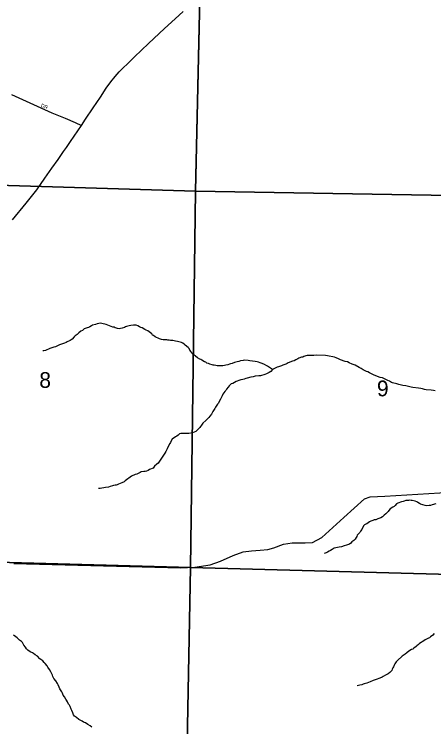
# Model space of a CAD drawing. Extents: x 0 to 34, y -2.3 to 22.
# Drawn here: x 3.889 to 5.006, y 17.952 to 19.85 of the extents above; entities that cross this region are included whole.
import ezdxf

# ---------------------------------------------------------------- set-up
doc = ezdxf.new("R2010")
doc.units = 0
for name, color, linetype in [('GM_X_Minor_River', 7, 'Continuous'), ('GM_X_Section', 7, 'Continuous'), ('GM_X_Section_Text', 7, 'Continuous'), ('GM_X_State_Route', 7, 'Continuous'), ('GM_X_Township_Road', 7, 'Continuous'), ('GM_X_Township_Subdivision', 7, 'Continuous'), ('GM_X_Township_Subdivision_Text', 7, 'Continuous')]:
    doc.layers.add(name, color=color, linetype=linetype)

msp = doc.modelspace()

# ---------------------------------------------------------------- linework, layer by layer
at = {"layer": 'GM_X_Minor_River'}
for p, q in [((4.0897, 19.0171), (4.0862, 19.0153)), ((4.0943, 19.02), (4.0897, 19.0171)), ((4.0974, 19.0214), (4.0943, 19.02)), ((4.1054, 19.0238), (4.0974, 19.0214)), ((4.1097, 19.0248), (4.1054, 19.0238)), ((4.1188, 19.0268), (4.1097, 19.0248)), ((4.126, 19.0255), (4.1188, 19.0268)), ((4.1298, 19.0246), (4.126, 19.0255)), ((4.1332, 19.0234), (4.1298, 19.0246)), ((4.1384, 19.0213), (4.1332, 19.0234)), ((4.1422, 19.0197), (4.1384, 19.0213)), ((4.1516, 19.0167), (4.1422, 19.0197)), ((4.155, 19.0159), (4.1516, 19.0167)), ((4.1576, 19.0147), (4.155, 19.0159)), ((4.182, 19.0158), (4.1762, 19.0137)), ((4.1847, 19.0169), (4.182, 19.0158)), ((4.1881, 19.0176), (4.1847, 19.0169)), ((4.1946, 19.0196), (4.1881, 19.0176)), ((4.1992, 19.021), (4.1946, 19.0196)), ((4.2061, 19.0216), (4.1992, 19.021)), ((4.2103, 19.0218), (4.2061, 19.0216)), ((4.2133, 19.0214), (4.2103, 19.0218)), ((4.2182, 19.0197), (4.2133, 19.0214)), ((4.2227, 19.0173), (4.2182, 19.0197)), ((4.2261, 19.0157), (4.2227, 19.0173)), ((4.2291, 19.0141), (4.2261, 19.0157)), ((4.0564, 18.9968), (4.0509, 18.9932)), ((4.0611, 19.0016), (4.0564, 18.9968)), ((4.0665, 19.0052), (4.0611, 19.0016)), ((4.0704, 19.0078), (4.0665, 19.0052)), ((4.0754, 19.0114), (4.0704, 19.0078)), ((4.0827, 19.0142), (4.0754, 19.0114)), ((4.0862, 19.0153), (4.0827, 19.0142)), ((4.1614, 19.0134), (4.1576, 19.0147)), ((4.164, 19.013), (4.1614, 19.0134)), ((4.1686, 19.0121), (4.164, 19.013)), ((4.172, 19.0127), (4.1686, 19.0121)), ((4.1762, 19.0137), (4.172, 19.0127)), ((4.2366, 19.0104), (4.2291, 19.0141)), ((4.2399, 19.0084), (4.2366, 19.0104)), ((4.2444, 19.0064), (4.2399, 19.0084)), ((4.2485, 19.0036), (4.2444, 19.0064)), ((4.2548, 18.9981), (4.2485, 19.0036)), ((4.2566, 18.995), (4.2548, 18.9981)), ((4.0373, 18.9807), (4.0299, 18.9771)), ((4.0427, 18.9839), (4.0373, 18.9807)), ((4.0486, 18.9906), (4.0427, 18.9839)), ((4.0509, 18.9932), (4.0486, 18.9906)), ((4.2593, 18.9942), (4.2566, 18.995)), ((4.2641, 18.9902), (4.2593, 18.9942)), ((4.2757, 18.9849), (4.2641, 18.9902)), ((4.281, 18.9833), (4.2757, 18.9849)), ((4.2852, 18.9827), (4.281, 18.9833)), ((4.289, 18.9823), (4.2852, 18.9827)), ((4.2947, 18.9821), (4.289, 18.9823)), ((4.2981, 18.9816), (4.2947, 18.9821)), ((4.3015, 18.9815), (4.2981, 18.9816)), ((4.3049, 18.981), (4.3015, 18.9815)), ((4.3075, 18.9806), (4.3049, 18.981)), ((4.311, 18.9805), (4.3075, 18.9806)), ((4.3147, 18.98), (4.311, 18.9805)), ((4.3178, 18.9791), (4.3147, 18.98)), ((4.3238, 18.9782), (4.3178, 18.9791)), ((4.331, 18.9761), (4.3238, 18.9782)), ((3.9838, 18.9598), (3.9803, 18.9577)), ((3.9938, 18.963), (3.9838, 18.9598)), ((3.9984, 18.964), (3.9938, 18.963)), ((4.0023, 18.9657), (3.9984, 18.964)), ((4.0096, 18.9693), (4.0023, 18.9657)), ((4.0176, 18.9717), (4.0096, 18.9693)), ((4.023, 18.9735), (4.0176, 18.9717)), ((4.0272, 18.9756), (4.023, 18.9735)), ((4.0299, 18.9771), (4.0272, 18.9756)), ((4.3344, 18.9752), (4.331, 18.9761)), ((4.3374, 18.974), (4.3344, 18.9752)), ((4.3411, 18.9712), (4.3374, 18.974)), ((4.3437, 18.9685), (4.3411, 18.9712)), ((4.3518, 18.9618), (4.3437, 18.9685)), ((4.3548, 18.959), (4.3518, 18.9618)), ((4.3566, 18.9552), (4.3548, 18.959)), ((3.9673, 18.9531), (3.9646, 18.9528)), ((3.9723, 18.9545), (3.9673, 18.9531)), ((3.9753, 18.9555), (3.9723, 18.9545)), ((3.9803, 18.9577), (3.9753, 18.9555)), ((4.3595, 18.9505), (4.3566, 18.9552)), ((4.3613, 18.9474), (4.3595, 18.9505)), ((4.3669, 18.9423), (4.3613, 18.9474)), ((4.3713, 18.9391), (4.3669, 18.9423)), ((4.669, 18.9405), (4.6656, 18.9395)), ((4.6804, 18.9409), (4.669, 18.9405)), ((4.6869, 18.9411), (4.6804, 18.9409)), ((4.693, 18.9413), (4.6869, 18.9411)), ((4.718, 18.9405), (4.693, 18.9413)), ((4.723, 18.9396), (4.718, 18.9405)), ((4.3765, 18.9348), (4.3713, 18.9391)), ((4.3833, 18.9312), (4.3765, 18.9348)), ((4.3859, 18.93), (4.3833, 18.9312)), ((4.3885, 18.9284), (4.3859, 18.93)), ((4.3956, 18.924), (4.3885, 18.9284)), ((4.3986, 18.9228), (4.3956, 18.924)), ((4.4019, 18.92), (4.3986, 18.9228)), ((4.4754, 18.922), (4.4692, 18.9195)), ((4.4826, 18.9237), (4.4754, 18.922)), ((4.4865, 18.9251), (4.4826, 18.9237)), ((4.4915, 18.9268), (4.4865, 18.9251)), ((4.498, 18.9278), (4.4915, 18.9268)), ((4.5014, 18.928), (4.498, 18.9278)), ((4.5113, 18.9277), (4.5014, 18.928)), ((4.5162, 18.9268), (4.5113, 18.9277)), ((4.5302, 18.9249), (4.5162, 18.9268)), ((4.5355, 18.924), (4.5302, 18.9249)), ((4.5393, 18.9231), (4.5355, 18.924)), ((4.5438, 18.9215), (4.5393, 18.9231)), ((4.5464, 18.9202), (4.5438, 18.9215)), ((4.6183, 18.9211), (4.6156, 18.9197)), ((4.6294, 18.9253), (4.6183, 18.9211)), ((4.6344, 18.9267), (4.6294, 18.9253)), ((4.6386, 18.9292), (4.6344, 18.9267)), ((4.6441, 18.9321), (4.6386, 18.9292)), ((4.6471, 18.9339), (4.6441, 18.9321)), ((4.6537, 18.936), (4.6471, 18.9339)), ((4.6571, 18.9363), (4.6537, 18.936)), ((4.6602, 18.9377), (4.6571, 18.9363)), ((4.6656, 18.9395), (4.6602, 18.9377)), ((4.7415, 18.9364), (4.723, 18.9396)), ((4.746, 18.9348), (4.7415, 18.9364)), ((4.7524, 18.9319), (4.746, 18.9348)), ((4.7572, 18.9291), (4.7524, 18.9319)), ((4.77, 18.9249), (4.7572, 18.9291)), ((4.7761, 18.9236), (4.77, 18.9249)), ((4.781, 18.9212), (4.7761, 18.9236)), ((4.7888, 18.9175), (4.781, 18.9212)), ((4.4061, 18.9191), (4.4019, 18.92)), ((4.4099, 18.9175), (4.4061, 18.9191)), ((4.4159, 18.9162), (4.4099, 18.9175)), ((4.4185, 18.9153), (4.4159, 18.9162)), ((4.4216, 18.9149), (4.4185, 18.9153)), ((4.4257, 18.914), (4.4216, 18.9149)), ((4.4291, 18.9135), (4.4257, 18.914)), ((4.4413, 18.9131), (4.4291, 18.9135)), ((4.4443, 18.9134), (4.4413, 18.9131)), ((4.4489, 18.9144), (4.4443, 18.9134)), ((4.4524, 18.9151), (4.4489, 18.9144)), ((4.4577, 18.9161), (4.4524, 18.9151)), ((4.4619, 18.9174), (4.4577, 18.9161)), ((4.465, 18.9189), (4.4619, 18.9174)), ((4.4692, 18.9195), (4.465, 18.9189)), ((4.5539, 18.9174), (4.5464, 18.9202)), ((4.5636, 18.9121), (4.5539, 18.9174)), ((4.5763, 18.9038), (4.5636, 18.9121)), ((4.5763, 18.9038), (4.572, 18.8986)), ((4.5887, 18.9095), (4.5763, 18.9038)), ((4.5921, 18.9105), (4.5887, 18.9095)), ((4.6005, 18.9129), (4.5921, 18.9105)), ((4.604, 18.9147), (4.6005, 18.9129)), ((4.6094, 18.9168), (4.604, 18.9147)), ((4.6121, 18.9179), (4.6094, 18.9168)), ((4.6156, 18.9197), (4.6121, 18.9179)), ((4.7971, 18.915), (4.7888, 18.9175)), ((4.8076, 18.9086), (4.7971, 18.915)), ((4.8124, 18.9058), (4.8076, 18.9086)), ((4.818, 18.9022), (4.8124, 18.9058)), ((4.8267, 18.8982), (4.818, 18.9022)), ((4.5191, 18.8831), (4.5091, 18.8807)), ((4.5248, 18.8844), (4.5191, 18.8831)), ((4.5279, 18.8851), (4.5248, 18.8844)), ((4.5306, 18.8858), (4.5279, 18.8851)), ((4.5401, 18.8866), (4.5306, 18.8858)), ((4.5447, 18.8869), (4.5401, 18.8866)), ((4.5473, 18.8875), (4.5447, 18.8869)), ((4.5531, 18.8889), (4.5473, 18.8875)), ((4.5558, 18.8899), (4.5531, 18.8889)), ((4.5604, 18.8917), (4.5558, 18.8899)), ((4.5677, 18.8953), (4.5604, 18.8917)), ((4.572, 18.8986), (4.5677, 18.8953)), ((4.8308, 18.8969), (4.8267, 18.8982)), ((4.8353, 18.8949), (4.8308, 18.8969)), ((4.8417, 18.8913), (4.8353, 18.8949)), ((4.8469, 18.8884), (4.8417, 18.8913)), ((4.8631, 18.8826), (4.8469, 18.8884)), ((4.4669, 18.8653), (4.461, 18.8597)), ((4.4707, 18.8663), (4.4669, 18.8653)), ((4.4757, 18.8688), (4.4707, 18.8663)), ((4.48, 18.8713), (4.4757, 18.8688)), ((4.4896, 18.8748), (4.48, 18.8713)), ((4.4926, 18.8759), (4.4896, 18.8748)), ((4.4976, 18.8769), (4.4926, 18.8759)), ((4.5007, 18.8779), (4.4976, 18.8769)), ((4.5057, 18.8797), (4.5007, 18.8779)), ((4.5091, 18.8807), (4.5057, 18.8797)), ((4.8695, 18.8809), (4.8631, 18.8826)), ((4.8751, 18.8785), (4.8695, 18.8809)), ((4.8841, 18.8744), (4.8751, 18.8785)), ((4.8882, 18.8724), (4.8841, 18.8744)), ((4.8931, 18.8692), (4.8882, 18.8724)), ((4.8965, 18.8676), (4.8931, 18.8692)), ((4.9078, 18.865), (4.8965, 18.8676)), ((4.9131, 18.8637), (4.9078, 18.865)), ((4.4492, 18.8449), (4.444, 18.8378)), ((4.4519, 18.8475), (4.4492, 18.8449)), ((4.4543, 18.8512), (4.4519, 18.8475)), ((4.4582, 18.8564), (4.4543, 18.8512)), ((4.461, 18.8597), (4.4582, 18.8564)), ((4.924, 18.8607), (4.9131, 18.8637)), ((4.932, 18.8597), (4.924, 18.8607)), ((4.9384, 18.858), (4.932, 18.8597)), ((4.9459, 18.8562), (4.9384, 18.858)), ((4.9501, 18.8554), (4.9459, 18.8562)), ((4.9656, 18.8537), (4.9501, 18.8554)), ((4.9713, 18.8528), (4.9656, 18.8537)), ((4.9758, 18.8519), (4.9713, 18.8528)), ((4.9815, 18.8502), (4.9758, 18.8519)), ((4.9856, 18.8493), (4.9815, 18.8502)), ((4.9989, 18.8482), (4.9856, 18.8493)), ((5.005, 18.8476), (4.9989, 18.8482)), ((5.0095, 18.8471), (5.005, 18.8476)), ((4.4399, 18.8277), (4.4383, 18.8243)), ((4.4424, 18.8337), (4.4399, 18.8277)), ((4.444, 18.8378), (4.4424, 18.8337)), ((4.4303, 18.8113), (4.4248, 18.8031)), ((4.4327, 18.8142), (4.4303, 18.8113)), ((4.4347, 18.8187), (4.4327, 18.8142)), ((4.4383, 18.8243), (4.4347, 18.8187)), ((4.416, 18.7882), (4.414, 18.7848)), ((4.4172, 18.7912), (4.416, 18.7882)), ((4.4231, 18.7993), (4.4172, 18.7912)), ((4.4248, 18.8031), (4.4231, 18.7993)), ((4.4045, 18.7733), (4.3994, 18.7678)), ((4.4072, 18.7755), (4.4045, 18.7733)), ((4.4096, 18.7788), (4.4072, 18.7755)), ((4.414, 18.7848), (4.4096, 18.7788)), ((4.3896, 18.7578), (4.3829, 18.7493)), ((4.3912, 18.7608), (4.3896, 18.7578)), ((4.3994, 18.7678), (4.3912, 18.7608)), ((4.3292, 18.7319), (4.3253, 18.7286)), ((4.3322, 18.7329), (4.3292, 18.7319)), ((4.3368, 18.7332), (4.3322, 18.7329)), ((4.3505, 18.7328), (4.3368, 18.7332)), ((4.3539, 18.733), (4.3505, 18.7328)), ((4.3639, 18.735), (4.3539, 18.733)), ((4.3723, 18.7386), (4.3639, 18.735)), ((4.3805, 18.7463), (4.3723, 18.7386)), ((4.3829, 18.7493), (4.3805, 18.7463)), ((4.3058, 18.7121), (4.3049, 18.709)), ((4.309, 18.718), (4.3058, 18.7121)), ((4.3179, 18.7239), (4.309, 18.718)), ((4.3222, 18.726), (4.3179, 18.7239)), ((4.3253, 18.7286), (4.3222, 18.726)), ((4.2985, 18.6982), (4.2961, 18.6926)), ((4.303, 18.7064), (4.2985, 18.6982)), ((4.3049, 18.709), (4.303, 18.7064)), ((4.2901, 18.6806), (4.2841, 18.6724)), ((4.2924, 18.6847), (4.2901, 18.6806)), ((4.2961, 18.6926), (4.2924, 18.6847)), ((4.2757, 18.659), (4.2722, 18.6542)), ((4.2809, 18.6672), (4.2757, 18.659)), ((4.2841, 18.6724), (4.2809, 18.6672)), ((4.2492, 18.637), (4.2454, 18.6349)), ((4.2585, 18.6405), (4.2492, 18.637)), ((4.2608, 18.6431), (4.2585, 18.6405)), ((4.2624, 18.6457), (4.2608, 18.6431)), ((4.2683, 18.6513), (4.2624, 18.6457)), ((4.2722, 18.6542), (4.2683, 18.6513)), ((4.2012, 18.6198), (4.1973, 18.6165)), ((4.2108, 18.6237), (4.2012, 18.6198)), ((4.2154, 18.6251), (4.2108, 18.6237)), ((4.2189, 18.6265), (4.2154, 18.6251)), ((4.2239, 18.629), (4.2189, 18.6265)), ((4.227, 18.6305), (4.2239, 18.629)), ((4.2343, 18.6318), (4.227, 18.6305)), ((4.2377, 18.6321), (4.2343, 18.6318)), ((4.2408, 18.6327), (4.2377, 18.6321)), ((4.2454, 18.6349), (4.2408, 18.6327)), ((4.1664, 18.5985), (4.1633, 18.5967)), ((4.1756, 18.6012), (4.1664, 18.5985)), ((4.1818, 18.6041), (4.1756, 18.6012)), ((4.1845, 18.6067), (4.1818, 18.6041)), ((4.188, 18.6096), (4.1845, 18.6067)), ((4.1973, 18.6165), (4.188, 18.6096)), ((4.1174, 18.5866), (4.1136, 18.5864)), ((4.1319, 18.5893), (4.1174, 18.5866)), ((4.1395, 18.5902), (4.1319, 18.5893)), ((4.1445, 18.5919), (4.1395, 18.5902)), ((4.1503, 18.5933), (4.1445, 18.5919)), ((4.153, 18.5943), (4.1503, 18.5933)), ((4.1572, 18.5953), (4.153, 18.5943)), ((4.1602, 18.5956), (4.1572, 18.5953)), ((4.1633, 18.5967), (4.1602, 18.5956)), ((4.9029, 18.5415), (4.9002, 18.5385)), ((4.9072, 18.5455), (4.9029, 18.5415)), ((4.9103, 18.5477), (4.9072, 18.5455)), ((4.9199, 18.5509), (4.9103, 18.5477)), ((4.9241, 18.5515), (4.9199, 18.5509)), ((4.9272, 18.5529), (4.9241, 18.5515)), ((4.9318, 18.5543), (4.9272, 18.5529)), ((4.9352, 18.555), (4.9318, 18.5543)), ((4.9383, 18.5549), (4.9352, 18.555)), ((4.9417, 18.5551), (4.9383, 18.5549)), ((4.9459, 18.5546), (4.9417, 18.5551)), ((4.9485, 18.5542), (4.9459, 18.5546)), ((4.9561, 18.5524), (4.9485, 18.5542)), ((4.9606, 18.5512), (4.9561, 18.5524)), ((4.9636, 18.5492), (4.9606, 18.5512)), ((4.9677, 18.5464), (4.9636, 18.5492)), ((4.971, 18.5448), (4.9677, 18.5464)), ((4.9831, 18.541), (4.971, 18.5448)), ((4.9941, 18.5414), (4.9873, 18.5405)), ((4.9976, 18.5417), (4.9941, 18.5414)), ((5.0014, 18.5427), (4.9976, 18.5417)), ((5.0117, 18.5458), (5.0014, 18.5427)), ((4.8842, 18.5257), (4.881, 18.5213)), ((4.8866, 18.5283), (4.8842, 18.5257)), ((4.8901, 18.532), (4.8866, 18.5283)), ((4.8971, 18.5367), (4.8901, 18.532)), ((4.9002, 18.5385), (4.8971, 18.5367)), ((4.9873, 18.5405), (4.9831, 18.541)), ((4.8513, 18.5035), (4.8471, 18.5029)), ((4.857, 18.506), (4.8513, 18.5035)), ((4.8647, 18.5088), (4.857, 18.506)), ((4.8693, 18.511), (4.8647, 18.5088)), ((4.874, 18.5154), (4.8693, 18.511)), ((4.8783, 18.5187), (4.874, 18.5154)), ((4.881, 18.5213), (4.8783, 18.5187)), ((4.8188, 18.4867), (4.814, 18.4777)), ((4.8216, 18.49), (4.8188, 18.4867)), ((4.8254, 18.4918), (4.8216, 18.49)), ((4.8281, 18.4928), (4.8254, 18.4918)), ((4.8351, 18.4979), (4.8281, 18.4928)), ((4.8382, 18.4994), (4.8351, 18.4979)), ((4.8436, 18.5015), (4.8382, 18.4994)), ((4.8471, 18.5029), (4.8436, 18.5015)), ((4.8092, 18.4695), (4.8021, 18.4621)), ((4.8108, 18.4725), (4.8092, 18.4695)), ((4.814, 18.4777), (4.8108, 18.4725)), ((4.793, 18.4483), (4.7876, 18.4443)), ((4.7965, 18.4516), (4.793, 18.4483)), ((4.7993, 18.4557), (4.7965, 18.4516)), ((4.8009, 18.4591), (4.7993, 18.4557)), ((4.8021, 18.4621), (4.8009, 18.4591)), ((4.7411, 18.4275), (4.7384, 18.426)), ((4.7541, 18.4305), (4.7411, 18.4275)), ((4.7602, 18.4314), (4.7541, 18.4305)), ((4.7675, 18.4339), (4.7602, 18.4314)), ((4.7732, 18.4352), (4.7675, 18.4339)), ((4.779, 18.4373), (4.7732, 18.4352)), ((4.7817, 18.4384), (4.779, 18.4373)), ((4.7848, 18.4413), (4.7817, 18.4384)), ((4.7876, 18.4443), (4.7848, 18.4413)), ((4.7198, 18.4148), (4.7141, 18.4131)), ((4.7233, 18.4166), (4.7198, 18.4148)), ((4.7272, 18.4195), (4.7233, 18.4166)), ((4.7314, 18.4217), (4.7272, 18.4195)), ((4.7353, 18.4238), (4.7314, 18.4217)), ((4.7384, 18.426), (4.7353, 18.4238)), ((5.007, 18.1999), (5.0035, 18.1962)), ((3.8934, 18.1915), (3.8867, 18.1958)), ((3.8967, 18.1891), (3.8934, 18.1915)), ((3.9026, 18.1828), (3.8967, 18.1891)), ((3.9078, 18.1792), (3.9026, 18.1828)), ((4.9794, 18.181), (4.9678, 18.1741)), ((4.9833, 18.1836), (4.9794, 18.181)), ((4.9922, 18.1878), (4.9833, 18.1836)), ((4.9949, 18.1889), (4.9922, 18.1878)), ((4.9976, 18.1911), (4.9949, 18.1889)), ((5.0035, 18.1962), (4.9976, 18.1911)), ((3.9104, 18.1761), (3.9078, 18.1792)), ((3.9126, 18.1726), (3.9104, 18.1761)), ((3.914, 18.1696), (3.9126, 18.1726)), ((3.9188, 18.1637), (3.914, 18.1696)), ((3.9217, 18.1595), (3.9188, 18.1637)), ((4.9526, 18.1617), (4.9499, 18.1587)), ((4.9588, 18.1653), (4.9526, 18.1617)), ((4.9612, 18.1679), (4.9588, 18.1653)), ((4.9651, 18.1712), (4.9612, 18.1679)), ((4.9678, 18.1741), (4.9651, 18.1712)), ((3.925, 18.1559), (3.9217, 18.1595)), ((3.9288, 18.1536), (3.925, 18.1559)), ((3.9332, 18.1504), (3.9288, 18.1536)), ((3.937, 18.1487), (3.9332, 18.1504)), ((3.9403, 18.1467), (3.937, 18.1487)), ((3.9448, 18.1432), (3.9403, 18.1467)), ((3.9504, 18.1404), (3.9448, 18.1432)), ((4.9301, 18.1449), (4.922, 18.1402)), ((4.934, 18.1486), (4.9301, 18.1449)), ((4.9399, 18.1529), (4.934, 18.1486)), ((4.9464, 18.1573), (4.9399, 18.1529)), ((4.9499, 18.1587), (4.9464, 18.1573)), ((3.9567, 18.133), (3.9504, 18.1404)), ((3.9645, 18.1274), (3.9567, 18.133)), ((3.9682, 18.1235), (3.9645, 18.1274)), ((4.9056, 18.1251), (4.902, 18.1195)), ((4.9095, 18.1284), (4.9056, 18.1251)), ((4.922, 18.1402), (4.9095, 18.1284)), ((3.9711, 18.12), (3.9682, 18.1235)), ((3.9763, 18.1138), (3.9711, 18.12)), ((3.9784, 18.1103), (3.9763, 18.1138)), ((3.9824, 18.1041), (3.9784, 18.1103)), ((4.8951, 18.1053), (4.8939, 18.1019)), ((4.8967, 18.1087), (4.8951, 18.1053)), ((4.8991, 18.1112), (4.8967, 18.1087)), ((4.9008, 18.1158), (4.8991, 18.1112)), ((4.902, 18.1195), (4.9008, 18.1158)), ((3.9864, 18.0983), (3.9824, 18.1041)), ((3.9904, 18.0894), (3.9864, 18.0983)), ((3.9918, 18.086), (3.9904, 18.0894)), ((3.9943, 18.0802), (3.9918, 18.086)), ((4.8714, 18.0859), (4.8687, 18.084)), ((4.8772, 18.0895), (4.8714, 18.0859)), ((4.8849, 18.0931), (4.8772, 18.0895)), ((4.8892, 18.0963), (4.8849, 18.0931)), ((4.8939, 18.1019), (4.8892, 18.0963)), ((3.9994, 18.074), (3.9943, 18.0802)), ((4.0038, 18.067), (3.9994, 18.074)), ((4.0056, 18.0635), (4.0038, 18.067)), ((4.8279, 18.0682), (4.821, 18.0665)), ((4.8325, 18.0699), (4.8279, 18.0682)), ((4.8364, 18.0717), (4.8325, 18.0699)), ((4.8444, 18.0749), (4.8364, 18.0717)), ((4.8472, 18.0763), (4.8444, 18.0749)), ((4.8556, 18.0791), (4.8472, 18.0763)), ((4.8594, 18.0801), (4.8556, 18.0791)), ((4.8625, 18.0816), (4.8594, 18.0801)), ((4.8687, 18.084), (4.8625, 18.0816)), ((4.0085, 18.0577), (4.0056, 18.0635)), ((4.0102, 18.0531), (4.0085, 18.0577)), ((4.0157, 18.0446), (4.0102, 18.0531)), ((4.8057, 18.062), (4.8018, 18.061)), ((4.8087, 18.0623), (4.8057, 18.062)), ((4.8145, 18.064), (4.8087, 18.0623)), ((4.8183, 18.0654), (4.8145, 18.064)), ((4.821, 18.0665), (4.8183, 18.0654)), ((4.0171, 18.0415), (4.0157, 18.0446)), ((4.0189, 18.0365), (4.0171, 18.0415)), ((4.0229, 18.0315), (4.0189, 18.0365)), ((4.0261, 18.0257), (4.0229, 18.0315)), ((4.0276, 18.023), (4.0261, 18.0257)), ((4.0305, 18.0183), (4.0276, 18.023)), ((4.0334, 18.0125), (4.0305, 18.0183)), ((4.0356, 18.0098), (4.0334, 18.0125)), ((4.0373, 18.0056), (4.0356, 18.0098)), ((4.0406, 17.999), (4.0373, 18.0056)), ((4.042, 17.9952), (4.0406, 17.999)), ((4.0448, 17.9887), (4.042, 17.9952)), ((4.047, 17.9837), (4.0448, 17.9887)), ((4.0495, 17.9805), (4.047, 17.9837)), ((4.0544, 17.9766), (4.0495, 17.9805)), ((4.0607, 17.9715), (4.0544, 17.9766)), ((4.0644, 17.9695), (4.0607, 17.9715)), ((4.07, 17.9666), (4.0644, 17.9695)), ((4.0734, 17.9643), (4.07, 17.9666)), ((4.0783, 17.9626), (4.0734, 17.9643)), ((4.085, 17.9582), (4.0783, 17.9626)), ((4.0914, 17.9546), (4.085, 17.9582)), ((4.0958, 17.9507), (4.0914, 17.9546))]:
    msp.add_line(p, q, dxfattribs=at)
at = {"layer": 'GM_X_Section'}
for p, q in [((4.3941, 20.4138), (4.3717, 19.3789)), ((4.3717, 19.3789), (4.3941, 20.4138)), ((4.3717, 19.3789), (3.5861, 19.4021)), ((3.5861, 19.4021), (4.3717, 19.3789)), ((4.3717, 19.3789), (4.3586, 18.376)), ((4.3586, 18.376), (4.3717, 19.3789)), ((5.3873, 19.3604), (4.3717, 19.3789)), ((4.3717, 19.3789), (5.3873, 19.3604)), ((4.3586, 18.376), (3.5658, 18.3983)), ((3.5658, 18.3983), (4.3586, 18.376)), ((4.3586, 18.376), (4.3385, 17.3752)), ((4.3385, 17.3752), (4.3586, 18.376)), ((5.3638, 18.3497), (4.3586, 18.376)), ((4.3586, 18.376), (5.3638, 18.3497))]:
    msp.add_line(p, q, dxfattribs=at)
at = {"layer": 'GM_X_State_Route'}
for p, q in [((4.3171, 19.8377), (4.3383, 19.8569)), ((4.2888, 19.8117), (4.3171, 19.8377)), ((4.2462, 19.7718), (4.2888, 19.8117)), ((4.209, 19.7364), (4.2462, 19.7718)), ((4.1776, 19.7057), (4.191, 19.7183)), ((4.191, 19.7183), (4.209, 19.7364)), ((4.1679, 19.6961), (4.1776, 19.7057)), ((4.1464, 19.6698), (4.1577, 19.6838)), ((4.1577, 19.6838), (4.1679, 19.6961)), ((4.1339, 19.6526), (4.1464, 19.6698)), ((4.1181, 19.6288), (4.1339, 19.6526)), ((4.0994, 19.6002), (4.1181, 19.6288)), ((4.0789, 19.5705), (4.0994, 19.6002)), ((4.0675, 19.5531), (4.0789, 19.5705)), ((4.0389, 19.5111), (4.0675, 19.5531)), ((4.0278, 19.495), (4.0389, 19.5111)), ((4.0202, 19.484), (4.0278, 19.495)), ((4.0057, 19.4631), (4.0202, 19.484)), ((3.9891, 19.4394), (4.0057, 19.4631)), ((3.9706, 19.413), (3.9891, 19.4394)), ((3.9485, 19.3824), (3.9706, 19.413)), ((3.9204, 19.3465), (3.9485, 19.3824)), ((3.8845, 19.302), (3.9204, 19.3465))]:
    msp.add_line(p, q, dxfattribs=at)
at = {"layer": 'GM_X_Township_Road'}
for p, q in [((4.8217, 18.5591), (4.8369, 18.5646)), ((4.8369, 18.5646), (4.8754, 18.5661)), ((4.8754, 18.5661), (5.0676, 18.5775)), ((4.7666, 18.5089), (4.8217, 18.5591)), ((4.7081, 18.456), (4.7666, 18.5089)), ((4.6835, 18.4428), (4.7081, 18.456)), ((4.5642, 18.4244), (4.58, 18.4285)), ((4.58, 18.4285), (4.6062, 18.4381)), ((4.6062, 18.4381), (4.6286, 18.4416)), ((4.6286, 18.4416), (4.6637, 18.4415)), ((4.6637, 18.4415), (4.6835, 18.4428)), ((4.4722, 18.4078), (4.498, 18.418)), ((4.498, 18.418), (4.5205, 18.4205)), ((4.5205, 18.4205), (4.5437, 18.4221)), ((4.5437, 18.4221), (4.5642, 18.4244)), ((4.4105, 18.3834), (4.4385, 18.3928)), ((4.4385, 18.3928), (4.4722, 18.4078)), ((3.8878, 18.3865), (4.3316, 18.3749)), ((4.3316, 18.3749), (4.3693, 18.3766)), ((4.3693, 18.3766), (4.4105, 18.3834))]:
    msp.add_line(p, q, dxfattribs=at)
at = {"layer": 'GM_X_Township_Subdivision'}
for p, q in [((3.8814, 19.6358), (3.989, 19.5875)), ((3.989, 19.5875), (4.0241, 19.5732)), ((4.0241, 19.5732), (4.051, 19.5615)), ((4.051, 19.5615), (4.0675, 19.5531))]:
    msp.add_line(p, q, dxfattribs=at)

# ---------------------------------------------------------------- texts
at = {"layer": 'GM_X_Section_Text'}
for s, p in [('8', (3.9555, 18.8546)), ('9', (4.8546, 18.8321))]:
    msp.add_text(s, height=0.0419, rotation=0, dxfattribs=at).set_placement(p)
at = {"layer": 'GM_X_Township_Subdivision_Text'}
msp.add_text('DR', height=0.00947, rotation=337.6191, dxfattribs=at).set_placement((3.9587, 19.6036))

doc.saveas('drawing.dxf')
